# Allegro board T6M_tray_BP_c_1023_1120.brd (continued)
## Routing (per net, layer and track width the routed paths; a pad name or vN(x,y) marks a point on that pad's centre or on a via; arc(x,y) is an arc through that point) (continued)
SAS_BLAD1_TX7_P: length 23.8
  TOP w0.178: U3.B8 171.89,24.81 171.69,24.61 171.69,24.13 v1(172.12,23.7)
  BOTTOM w0.178: J25.G5 166.89,10.86 166.72,11.02 166.25,11.02 arc(166.04,11.07) 165.87,11.18 arc(165.76,11.35) 165.71,11.56 165.71,20.95 arc(165.78,21.28) 165.97,21.55 169,24.59 arc(169.03,24.64) 169.04,24.69 arc(169.11,25.01) 169.29,25.28 169.53,25.53 arc(169.81,25.72) 170.14,25.78 170.73,25.78 arc(170.93,25.74) 171.09,25.63 171.49,25.23 171.66,24.88 171.66,24.16 v1(172.12,23.7)
SAS_BLAD1_TX8_N: length 26.6
  TOP w0.178: U3.B12 168.68,24.81 168.91,24.58 168.91,24.4 168.69,24.18 166.7,24.18 v1(166.22,24.66)
  IN2 w0.152: J25.F6 164.39,8.5 162.78,8.5 arc(162.58,8.54) 162.42,8.65 161.9,9.17 arc(161.79,9.34) 161.75,9.53 161.75,16.91 arc(161.79,17.1) 161.9,17.27 167.31,22.69 arc(167.42,22.85) 167.46,23.04 167.46,23.67 arc(167.42,23.86) 167.31,24.02 167.26,24.08 arc(167.09,24.19) 166.9,24.23 166.65,24.23 v1(166.22,24.66)
SAS_BLAD1_TX8_P: length 27.9
  TOP w0.178: v1(166.22,23.39) 166.65,23.83 168.84,23.83 169.26,24.25 169.26,24.58 169.49,24.81 U3.B11
  IN2 w0.152: J25.E6 164.39,8.1 162.78,8.1 arc(162.43,8.17) 162.13,8.36 161.61,8.89 arc(161.41,9.18) 161.34,9.53 161.34,16.91 arc(161.41,17.26) 161.61,17.56 162,17.95 162,18.19 162.33,18.51 162.57,18.51 162.89,18.84 162.89,19.07 163.21,19.4 163.45,19.4 163.77,19.72 163.77,19.96 164.1,20.28 164.33,20.28 164.66,20.61 164.66,20.84 164.98,21.17 165.22,21.17 165.54,21.49 165.54,21.73 165.87,22.05 166.1,22.05 167.03,22.97 arc(167.05,23.01) 167.06,23.04 167.06,23.67 arc(167.05,23.7) 167.03,23.74 166.97,23.8 arc(166.94,23.82) 166.9,23.83 166.65,23.83 v1(166.22,23.39)
SAS_BLAD2_RX1_N: length 36
  TOP w0.178: v1(415.26,30.56) 415.7,30.12 415.7,29.7 415.49,29.49 U2.A3
  BOTTOM w0.178: J8.E1 396.41,7.18 398.56,7.18 arc(398.62,7.19) 398.67,7.22 413.59,22.15 arc(413.63,22.2) 413.64,22.26 413.64,24.4 arc(413.7,24.73) 413.89,25.01 415.67,26.79 arc(415.71,26.84) 415.72,26.9 415.72,30.1 v1(415.26,30.56)
SAS_BLAD2_RX1_P: length 37.4
  TOP w0.178: v1(416.53,30.56) 416.05,30.09 416.05,29.74 416.3,29.49 U2.A2
  BOTTOM w0.178: J8.D1 396.41,6.82 398.56,6.82 arc(398.75,6.86) 398.92,6.97 404.13,12.19 404.37,12.19 404.75,12.57 404.75,12.81 405.37,13.42 405.61,13.42 405.99,13.8 405.99,14.04 406.37,14.43 406.62,14.43 407,14.81 407,15.05 407.38,15.44 407.63,15.44 408,15.82 408,16.06 408.39,16.45 408.63,16.45 409.01,16.83 409.01,17.07 409.4,17.46 409.64,17.46 410.02,17.83 410.02,18.08 413.84,21.9 arc(413.95,22.06) 413.99,22.26 413.99,24.4 arc(414.03,24.6) 414.14,24.76 415.92,26.54 arc(416.03,26.71) 416.07,26.9 416.07,30.1 v1(416.53,30.56)
SAS_BLAD2_RX2_N: length 36
  TOP w0.178: v1(412.87,31.68) 413.33,31.22 413.33,29.74 413.09,29.5 U2.A6
  IN2 w0.152: v1(412.87,31.68) 413.31,32.11 413.31,32.35 arc(413.3,32.39) 413.28,32.42 413.19,32.51 arc(413.16,32.53) 413.12,32.54 412.64,32.54 arc(412.54,32.53) 412.44,32.5 410.64,31.75 arc(410.59,31.73) 410.55,31.7 410.01,31.34 arc(409.97,31.31) 409.93,31.27 409.5,30.85 arc(409.47,30.81) 409.44,30.77 408.84,29.88 arc(408.82,29.83) 408.8,29.79 408.72,29.59 arc(408.71,29.57) 408.71,29.54 408.71,29.44 arc(408.7,29.34) 408.67,29.25 407.39,26.17 arc(407.35,26.09) 407.28,26.01 406.91,25.64 406.91,25.41 406.59,25.09 406.36,25.09 406.04,24.76 406.04,24.53 405.71,24.21 405.48,24.21 405.16,23.89 405.16,23.66 404.84,23.34 404.61,23.34 404.29,23.01 404.29,22.78 403.96,22.46 403.73,22.46 403.41,22.14 403.41,21.91 403.09,21.59 402.86,21.59 402.54,21.26 402.54,21.03 402.21,20.71 401.99,20.71 401.72,20.44 399.17,18.34 397.07,16.5 394.53,15.34 393.08,13.89 393.05,13.8 393.05,13.07 arc(393.07,12.93) 393.15,12.81 arc(393.27,12.73) 393.41,12.7 393.7,12.7 393.89,12.9 J8.I2
SAS_BLAD2_RX2_P: length 37.1
  TOP w0.178: v1(414.14,31.68) 413.68,31.22 413.68,29.71 413.9,29.5 U2.A5
  IN2 w0.152: v1(414.14,31.68) 413.71,32.11 413.71,32.35 arc(413.67,32.54) 413.56,32.71 413.48,32.79 arc(413.31,32.91) 413.12,32.94 412.64,32.94 arc(412.46,32.93) 412.29,32.87 410.48,32.12 arc(410.4,32.08) 410.32,32.04 409.78,31.67 arc(409.71,31.62) 409.64,31.56 409.22,31.13 arc(409.16,31.07) 409.1,30.99 408.51,30.1 arc(408.46,30.02) 408.42,29.94 408.34,29.75 arc(408.31,29.64) 408.3,29.54 408.3,29.44 arc(408.3,29.42) 408.29,29.4 407.02,26.33 arc(407.01,26.31) 407,26.3 401.45,20.75 arc(401.44,20.74) 401.44,20.74 398.91,18.65 arc(398.91,18.65) 398.9,18.65 398.9,18.64 396.84,16.84 394.29,15.68 392.74,14.12 392.64,13.89 392.64,13.07 arc(392.7,12.77) 392.87,12.52 arc(393.12,12.36) 393.41,12.3 393.69,12.3 393.89,12.1 J8.H2
SAS_BLAD2_RX3_N: length 37.5
  TOP w0.178: U2.A9 410.69,29.5 410.92,29.73 410.92,30.14 v1(410.46,30.59)
  BOTTOM w0.178: J8.C2 393.89,4.46 394.08,4.28 394.46,4.28 arc(394.52,4.29) 394.57,4.32 394.67,4.42 arc(394.7,4.47) 394.72,4.53 394.72,13.38 arc(394.75,13.58) 394.86,13.74 395.3,14.18 arc(395.46,14.29) 395.66,14.33 396.74,14.55 400.11,17.27 arc(400.11,17.27) 400.11,17.27 400.12,17.28 402.58,18.8 406.41,24.82 406.41,24.82 408.58,26.76 arc(408.58,26.76) 408.58,26.76 410.87,29.05 arc(410.91,29.11) 410.92,29.17 410.92,30.13 v1(410.46,30.59)
SAS_BLAD2_RX3_P: length 38.9
  TOP w0.178: U2.A8 411.49,29.5 411.27,29.73 411.27,30.14 v1(411.73,30.59)
  BOTTOM w0.178: J8.B2 393.89,3.68 394.14,3.92 394.46,3.92 arc(394.66,3.96) 394.82,4.07 394.92,4.17 arc(395.03,4.33) 395.07,4.53 395.07,13.38 arc(395.08,13.44) 395.11,13.5 395.55,13.93 arc(395.6,13.96) 395.66,13.98 395.69,13.98 396.9,14.23 400.32,16.99 402.84,18.54 403.22,19.14 403.22,19.14 403.46,19.2 403.74,19.65 403.69,19.89 403.69,19.88 403.98,20.34 403.98,20.35 404.22,20.4 404.51,20.85 404.45,21.09 404.46,21.09 404.75,21.55 404.75,21.55 404.98,21.61 405.27,22.06 405.22,22.29 405.22,22.3 405.51,22.75 405.51,22.76 405.75,22.81 406.03,23.26 405.98,23.5 405.99,23.5 406.68,24.59 408.81,26.5 arc(408.82,26.51) 408.83,26.52 409.1,26.79 409.35,26.79 409.73,27.17 409.73,27.41 410.11,27.8 410.36,27.8 410.73,28.17 410.73,28.42 411.12,28.81 arc(411.23,28.97) 411.27,29.17 411.27,30.14 v1(411.73,30.59)
SAS_BLAD2_RX4_N: length 36.1
  TOP w0.178: U2.A12 408.3,29.5 408.54,29.75 408.54,30.01 408.3,30.25 406.29,30.25 406.04,30 406.04,29.77 v1(406.5,29.31)
  IN2 w0.152: v1(406.5,29.31) 406.07,28.88 406.07,28.51 arc(406.03,28.31) 405.92,28.15 405.76,27.99 arc(405.59,27.88) 405.4,27.84 405,27.84 arc(404.81,27.8) 404.65,27.69 403.65,26.69 arc(403.54,26.53) 403.5,26.33 403.5,25.64 arc(403.43,25.29) 403.23,24.99 402.16,23.92 402.16,23.7 401.84,23.38 401.62,23.38 401.3,23.06 401.3,22.84 400.97,22.51 400.76,22.51 396.73,18.48 arc(396.69,18.45) 396.65,18.42 395.57,17.7 arc(395.53,17.67) 395.48,17.65 394.9,17.41 arc(394.8,17.38) 394.71,17.37 394.21,17.37 arc(394.02,17.33) 393.85,17.22 391.63,15.01 391.22,14.01 391.1,13.26 391.1,7.4 arc(391.11,7.35) 391.14,7.3 391.17,7.27 arc(391.24,7.22) 391.33,7.2 391.74,7.2 391.89,7.36 J8.E3
SAS_BLAD2_RX4_P: length 37.7
  TOP w0.178: v1(405.23,29.31) 405.69,29.77 405.69,30.14 406.15,30.6 408.44,30.6 408.9,30.15 408.9,29.7 409.09,29.5 U2.A11
  IN2 w0.152: J8.D3 391.89,6.66 391.76,6.8 391.33,6.8 arc(391.09,6.85) 390.88,6.98 390.86,7.01 arc(390.73,7.19) 390.69,7.4 390.69,13.29 390.83,14.13 391.29,15.24 393.56,17.51 arc(393.86,17.71) 394.21,17.78 394.71,17.78 arc(394.73,17.78) 394.74,17.79 395.33,18.03 arc(395.33,18.03) 395.34,18.04 396.42,18.76 arc(396.43,18.76) 396.44,18.77 402.94,25.28 arc(403.05,25.44) 403.09,25.64 403.09,26.33 arc(403.16,26.68) 403.36,26.98 404.36,27.98 arc(404.65,28.18) 405,28.24 405.4,28.24 arc(405.44,28.25) 405.47,28.27 405.63,28.44 arc(405.65,28.47) 405.66,28.51 405.66,28.88 v1(405.23,29.31)
SAS_BLAD2_RX5_N: length 28.9
  TOP w0.178: v1(396.25,31) 396.71,30.54 396.71,29.73 396.48,29.5 U4.A3
  IN2 w0.152: v1(396.25,31) 396.68,31.43 396.68,31.75 arc(396.67,31.79) 396.65,31.82 396.48,32 arc(396.44,32.02) 396.41,32.03 396.09,32.03 arc(396.05,32.02) 396.02,32 395.78,31.77 395.44,31.42 394.85,30.83 394.84,30.83 arc(394.82,30.79) 394.81,30.75 394.81,29.85 394.99,29.67 394.99,29.26 394.81,29.09 394.81,28.63 394.99,28.45 394.99,28.05 394.81,27.87 394.81,27.28 394.96,27.13 394.96,26.67 394.81,26.52 394.81,26.14 arc(394.85,25.95) 394.96,25.78 395.04,25.7 arc(395.15,25.54) 395.19,25.34 395.19,23.43 arc(395.15,23.23) 395.04,23.07 394.85,22.87 394.85,22.64 394.52,22.32 394.3,22.32 393.97,22 393.97,21.77 393.65,21.44 393.42,21.44 393.1,21.12 393.1,20.89 392.77,20.57 392.55,20.57 391.86,19.88 arc(391.75,19.72) 391.71,19.53 391.71,17.71 arc(391.67,17.52) 391.56,17.35 389.2,14.98 arc(389.09,14.82) 389.05,14.62 389.05,13.09 arc(389.08,12.94) 389.16,12.82 389.16,12.82 arc(389.28,12.73) 389.43,12.7 389.74,12.7 389.89,12.86 J8.I4
SAS_BLAD2_RX5_P: length 30
  TOP w0.178: U4.A2 397.28,29.5 397.06,29.73 397.06,30.54 v1(397.52,31)
  IN2 w0.152: J8.H4 389.89,12.11 389.7,12.3 389.43,12.3 arc(389.13,12.36) 388.87,12.53 arc(388.7,12.79) 388.64,13.09 388.64,14.62 arc(388.71,14.97) 388.91,15.27 391.28,17.64 arc(391.3,17.67) 391.31,17.71 391.31,19.53 arc(391.38,19.88) 391.58,20.17 394.76,23.35 arc(394.78,23.39) 394.79,23.43 394.79,25.34 arc(394.78,25.38) 394.76,25.41 394.67,25.5 arc(394.48,25.79) 394.41,26.14 394.41,30.75 arc(394.45,30.95) 394.56,31.12 395.15,31.71 395.73,32.29 arc(395.89,32.4) 396.09,32.44 396.41,32.44 arc(396.6,32.4) 396.76,32.29 396.94,32.11 arc(397.05,31.95) 397.09,31.75 397.09,31.43 v1(397.52,31)
SAS_BLAD2_RX6_N: length 34.2
  TOP w0.178: U4.A6 394.08,29.5 394.31,29.73 394.31,32.48 v1(393.88,32.92)
  BOTTOM w0.178: v1(393.88,32.92) 394.34,32.46 394.34,27.43 arc(394.4,27.1) 394.59,26.83 394.67,26.74 arc(394.7,26.69) 394.72,26.63 394.72,22.5 394.71,22.37 394.7,22.32 394.7,22.32 394.44,21.68 arc(394.42,21.65) 394.4,21.63 389.76,16.98 arc(389.73,16.95) 389.72,16.92 389.01,15.2 arc(389,15.19) 389,15.17 388.83,14.46 388.73,14.05 388.72,13.97 388.72,7.37 arc(388.71,7.3) 388.66,7.23 388.66,7.23 arc(388.6,7.19) 388.53,7.18 388.07,7.18 387.89,7.36 J8.E5
SAS_BLAD2_RX6_P: length 35.6
  TOP w0.178: U4.A5 394.88,29.5 394.66,29.73 394.66,32.43 v1(395.15,32.92)
  BOTTOM w0.178: v1(395.15,32.92) 394.69,32.46 394.69,31.47 394.86,31.3 394.86,30.76 394.69,30.59 394.69,28.67 394.86,28.5 394.86,27.97 394.69,27.79 394.69,27.43 arc(394.72,27.24) 394.83,27.07 394.92,26.99 arc(395.03,26.83) 395.07,26.63 395.07,26.22 395.24,26.05 395.24,25.52 395.07,25.34 395.07,24.8 395.24,24.62 395.24,24.09 395.07,23.92 395.07,23.37 395.24,23.2 395.24,22.66 395.07,22.49 395.06,22.33 395.03,22.18 394.76,21.54 arc(394.72,21.46) 394.65,21.38 394.54,21.26 394.33,21.06 394.33,20.82 393.96,20.44 393.71,20.44 390.03,16.76 389.34,15.08 389.07,13.97 389.07,7.37 arc(389.03,7.16) 388.91,6.98 388.91,6.98 arc(388.74,6.86) 388.53,6.82 388.08,6.82 387.89,6.63 J8.D5
SAS_BLAD2_RX7_N: length 33.9
  TOP w0.178: v1(391.45,31.99) 391.91,31.53 391.91,29.73 391.68,29.5 U4.A9
  IN2 w0.152: v1(391.45,31.99) 391.88,32.42 391.88,32.77 arc(391.87,32.81) 391.85,32.84 391.73,32.96 arc(391.69,32.99) 391.66,32.99 390.25,32.99 arc(390.05,32.96) 389.89,32.85 387.65,30.6 arc(387.54,30.44) 387.5,30.24 387.5,28.76 arc(387.54,28.57) 387.65,28.4 388.69,27.36 388.8,27.36 388.92,27.36 389.24,27.04 389.24,26.8 390.29,25.75 arc(390.4,25.59) 390.44,25.39 390.44,22.74 arc(390.37,22.39) 390.18,22.09 389.95,21.87 389.95,21.74 389.95,21.61 389.63,21.29 389.37,21.29 389.04,20.96 389.04,20.83 389.04,20.7 388.72,20.38 388.46,20.38 386.45,18.37 386.45,18.24 386.45,18.11 386.13,17.79 385.87,17.79 385.54,17.46 385.54,17.33 385.54,17.2 385.22,16.88 384.96,16.88 384.75,16.67 arc(384.64,16.5) 384.6,16.31 384.6,13.04 arc(384.63,12.91) 384.7,12.8 arc(384.81,12.73) 384.94,12.7 385.7,12.7 385.89,12.9 J8.I6
SAS_BLAD2_RX7_P: length 35.1
  TOP w0.178: v1(392.72,31.99) 392.26,31.53 392.26,29.73 392.48,29.5 U4.A8
  IN2 w0.152: v1(392.72,31.99) 392.29,32.42 392.29,32.77 arc(392.25,32.96) 392.14,33.13 392.01,33.25 arc(391.85,33.36) 391.66,33.4 390.25,33.4 arc(389.9,33.33) 389.6,33.13 387.36,30.89 arc(387.16,30.59) 387.09,30.24 387.09,28.76 arc(387.16,28.41) 387.36,28.11 390.01,25.46 arc(390.03,25.43) 390.04,25.39 390.04,22.74 arc(390,22.55) 389.89,22.38 384.46,16.96 arc(384.26,16.66) 384.2,16.31 384.2,13.04 arc(384.25,12.76) 384.41,12.52 arc(384.66,12.35) 384.94,12.3 385.72,12.3 385.89,12.12 J8.H6
SAS_BLAD2_RX8_N: length 35.5
  TOP w0.178: v1(389.05,30.73) 389.51,30.27 389.51,29.73 389.28,29.5 U4.A12
  BOTTOM w0.178: v1(389.05,30.73) 389.51,31.19 389.51,31.51 arc(389.5,31.57) 389.46,31.62 389.46,31.63 arc(389.4,31.67) 389.34,31.68 388.75,31.68 arc(388.56,31.64) 388.39,31.53 387.39,30.52 arc(387.28,30.36) 387.24,30.16 387.24,27.21 arc(387.2,27.01) 387.09,26.85 384.47,24.22 arc(384.36,24.06) 384.32,23.86 384.32,23.14 384.49,22.97 384.49,22.44 384.32,22.26 384.32,21.73 384.49,21.56 384.49,21.02 384.32,20.85 384.32,4.94 arc(384.36,4.75) 384.47,4.58 384.62,4.42 arc(384.79,4.31) 384.98,4.28 385.37,4.28 J8.C6
SAS_BLAD2_RX8_P: length 36.8
  TOP w0.178: U4.A11 390.08,29.5 389.86,29.73 389.86,30.27 v1(390.32,30.73)
  BOTTOM w0.178: v1(390.32,30.73) 389.86,31.19 389.86,31.51 arc(389.82,31.71) 389.71,31.87 389.7,31.88 arc(389.54,31.99) 389.34,32.03 388.75,32.03 arc(388.43,31.96) 388.15,31.78 387.14,30.77 arc(386.95,30.49) 386.89,30.16 386.89,27.21 arc(386.88,27.15) 386.84,27.09 384.22,24.47 arc(384.03,24.19) 383.97,23.86 383.97,4.94 arc(384.03,4.61) 384.22,4.33 384.37,4.18 arc(384.65,3.99) 384.98,3.92 385.37,3.92 J8.B6
SAS_BLAD2_TX1_N: length 39.6
  TOP w0.178: v1(418.66,23.4) 418.21,23.85 416.53,23.85 416.12,24.26 416.12,24.58 415.9,24.81 U2.B3
  IN2 w0.152: v1(418.66,23.4) 419.09,23.83 419.41,23.83 arc(419.53,23.81) 419.64,23.74 arc(419.71,23.64) 419.73,23.52 419.73,22.94 arc(419.73,22.92) 419.72,22.9 419.15,21.53 arc(419.15,21.52) 419.14,21.51 413.78,13.48 413.77,13.47 406.46,6.16 arc(406.44,6.14) 406.41,6.12 arc(406.4,6.11) 406.39,6.11 arc(406.37,6.1) 406.36,6.09 399.01,3.04 arc(398.92,3.01) 398.82,3 396.39,3 J8.B1
SAS_BLAD2_TX1_P: length 41.1
  TOP w0.178: U2.B2 416.69,24.81 416.47,24.58 416.47,24.41 416.68,24.2 418.19,24.2 v1(418.66,24.67)
  IN2 w0.152: v1(418.66,24.67) 419.09,24.24 419.41,24.24 arc(419.69,24.18) 419.92,24.03 arc(420.08,23.79) 420.14,23.52 420.14,22.94 arc(420.13,22.84) 420.1,22.75 419.53,21.37 arc(419.51,21.33) 419.48,21.28 419.48,21.28 414.11,13.25 414.09,13.21 413.05,12.18 413.05,11.94 412.73,11.62 412.49,11.62 412.17,11.3 412.17,11.06 411.85,10.73 411.61,10.73 411.28,10.41 411.28,10.17 410.96,9.85 410.72,9.85 410.4,9.53 410.4,9.29 410.08,8.96 409.84,8.96 409.52,8.64 409.52,8.4 409.19,8.08 408.95,8.08 408.63,7.76 408.63,7.52 408.31,7.2 408.07,7.2 406.74,5.87 arc(406.69,5.83) 406.64,5.78 arc(406.61,5.77) 406.58,5.75 arc(406.55,5.73) 406.52,5.72 399.17,2.66 arc(398.99,2.61) 398.82,2.59 396.38,2.59 J8.A1
SAS_BLAD2_TX2_N: length 29.4
  TOP w0.178: U2.B6 413.49,24.99 413.72,24.76 413.72,18.98 v1(413.26,18.52)
  IN2 w0.152: v1(413.26,18.52) 413.69,18.08 413.69,17.62 arc(413.65,17.42) 413.54,17.26 407.84,11.55 arc(407.67,11.44) 407.48,11.4 396.39,11.4 J8.H1
SAS_BLAD2_TX2_P: length 30.5
  TOP w0.178: v1(414.53,18.52) 414.07,18.98 414.07,24.76 414.3,24.99 U2.B5
  IN2 w0.152: J8.G1 396.39,11 400.03,11 400.2,10.82 400.66,10.82 400.84,11 401.3,11 401.47,10.82 401.93,10.82 402.1,11 402.56,11 402.74,10.82 403.2,10.82 403.37,11 407.48,11 arc(407.83,11.07) 408.13,11.26 413.83,16.97 arc(414.03,17.27) 414.1,17.62 414.1,18.09 v1(414.53,18.52)
SAS_BLAD2_TX3_N: length 30.3
  TOP w0.178: v1(410.86,23.58) 411.32,24.04 411.32,24.58 411.09,24.81 U2.B9
  IN2 w0.152: J8.F2 393.89,8.73 394.12,8.5 394.5,8.5 arc(394.57,8.52) 394.63,8.56 arc(394.68,8.62) 394.69,8.7 394.69,13.28 arc(394.76,13.63) 394.96,13.93 395.14,14.11 arc(395.43,14.31) 395.78,14.38 403.14,14.38 arc(403.33,14.42) 403.5,14.53 411.14,22.17 arc(411.25,22.34) 411.29,22.53 411.29,23.15 v1(410.86,23.58)
SAS_BLAD2_TX3_P: length 31.6
  TOP w0.178: U2.B8 411.9,24.81 411.67,24.58 411.67,24.04 v1(412.13,23.58)
  IN2 w0.152: v1(412.13,23.58) 411.7,23.15 411.7,22.53 arc(411.63,22.18) 411.43,21.89 403.78,14.24 arc(403.49,14.04) 403.14,13.97 402.74,13.97 402.59,13.82 402.13,13.82 401.98,13.97 401.52,13.97 401.37,13.82 400.91,13.82 400.76,13.97 400.3,13.97 400.15,13.82 399.69,13.82 399.54,13.97 399.08,13.97 398.93,13.82 398.47,13.82 398.32,13.97 397.86,13.97 397.71,13.82 397.25,13.82 397.1,13.97 395.78,13.97 arc(395.59,13.93) 395.43,13.82 395.25,13.64 arc(395.14,13.48) 395.1,13.28 395.1,8.7 arc(395.05,8.47) 394.92,8.27 arc(394.73,8.14) 394.5,8.1 394.09,8.1 393.89,7.89 J8.E2
SAS_BLAD2_TX4_N: length 34.3
  TOP w0.178: v1(406.27,26.82) 405.81,26.37 405.81,25.08 407.15,23.74 408.56,23.74 408.92,24.1 408.92,24.58 408.69,24.81 U2.B12
  BOTTOM w0.178: J8.H3 391.89,11.56 392.08,11.38 392.53,11.38 arc(392.6,11.39) 392.66,11.43 arc(392.7,11.49) 392.71,11.56 392.71,13.98 392.95,14.56 394.39,16 arc(394.67,16.19) 395,16.25 395.26,16.25 arc(395.28,16.25) 395.29,16.26 396.11,16.6 arc(396.14,16.61) 396.16,16.63 398.71,19.18 arc(398.99,19.37) 399.32,19.43 399.6,19.43 arc(399.62,19.43) 399.64,19.44 400.42,19.76 arc(400.45,19.78) 400.47,19.8 401.62,20.95 arc(401.64,20.97) 401.66,21 402.6,23.28 arc(402.61,23.31) 402.62,23.34 402.62,26.54 arc(402.68,26.86) 402.87,27.14 403.77,28.04 arc(404.05,28.23) 404.37,28.3 405.09,28.3 arc(405.29,28.26) 405.45,28.15 405.66,27.94 arc(405.77,27.77) 405.81,27.58 405.81,27.28 v1(406.27,26.82)
SAS_BLAD2_TX4_P: length 35.4
  TOP w0.178: v1(405,26.82) 405.46,26.36 405.46,24.94 407,23.39 408.71,23.39 409.27,23.96 409.27,24.58 409.49,24.81 U2.B11
  BOTTOM w0.178: v1(405,26.82) 405.46,27.28 405.46,27.58 arc(405.45,27.64) 405.41,27.69 405.2,27.9 arc(405.15,27.93) 405.09,27.95 404.37,27.95 arc(404.18,27.91) 404.02,27.8 403.11,26.9 arc(403,26.73) 402.97,26.54 402.97,26.22 403.14,26.04 403.14,25.51 402.97,25.34 402.97,24.79 403.14,24.62 403.14,24.09 402.97,23.91 402.97,23.34 arc(402.96,23.24) 402.93,23.15 401.98,20.86 arc(401.93,20.78) 401.87,20.7 400.72,19.55 arc(400.64,19.48) 400.56,19.44 399.78,19.11 arc(399.69,19.09) 399.6,19.08 399.32,19.08 arc(399.13,19.04) 398.96,18.93 398.64,18.61 398.64,18.4 398.27,18.02 398.05,18.02 396.41,16.38 arc(396.34,16.32) 396.25,16.27 395.43,15.93 arc(395.35,15.91) 395.26,15.9 395,15.9 arc(394.8,15.86) 394.64,15.75 393.25,14.36 393.06,13.91 393.06,11.55 arc(393.02,11.35) 392.91,11.18 arc(392.73,11.07) 392.53,11.02 392,11.02 391.89,10.92 J8.G3
SAS_BLAD2_TX5_N: length 26.8
  TOP w0.178: v1(399.22,23.39) 398.79,23.83 397.54,23.83 397.11,24.26 397.11,24.58 396.88,24.81 U4.B3
  BOTTOM w0.178: v1(399.22,23.39) 399.68,23.85 399.99,23.85 arc(400.05,23.84) 400.1,23.81 400.21,23.7 arc(400.24,23.65) 400.25,23.59 400.25,22.8 arc(400.21,22.6) 400.1,22.44 399.2,21.54 arc(399.04,21.43) 398.84,21.39 397.52,21.39 arc(397.33,21.35) 397.16,21.24 394.11,18.18 arc(394.08,18.16) 394.05,18.16 arc(393.75,18.1) 393.5,17.93 391.35,15.78 arc(391.33,15.75) 391.31,15.72 390.92,14.77 arc(390.91,14.76) 390.91,14.75 390.9,14.7 390.72,13.98 390.71,13.89 390.71,8.66 arc(390.7,8.59) 390.66,8.53 arc(390.59,8.49) 390.52,8.48 390.08,8.48 389.89,8.66 J8.F4
SAS_BLAD2_TX5_P: length 28
  TOP w0.178: U4.B2 397.68,24.81 397.46,24.58 397.46,24.41 397.69,24.18 398.74,24.18 v1(399.22,24.66)
  BOTTOM w0.178: v1(399.22,24.66) 399.68,24.2 399.99,24.2 arc(400.18,24.16) 400.35,24.05 400.45,23.95 arc(400.56,23.78) 400.6,23.59 400.6,22.8 arc(400.54,22.47) 400.35,22.19 400.19,22.02 400.19,21.78 399.81,21.4 399.57,21.4 399.45,21.29 arc(399.17,21.1) 398.84,21.04 398.64,21.04 398.47,20.86 397.93,20.86 397.76,21.04 397.52,21.04 arc(397.46,21.02) 397.41,20.99 397.16,20.73 397.16,20.49 396.78,20.11 396.53,20.11 396.53,20.11 396.15,19.72 396.15,19.48 395.77,19.1 395.53,19.1 395.14,18.72 395.14,18.47 394.76,18.09 394.52,18.09 394.35,17.93 arc(394.21,17.84) 394.05,17.81 arc(393.89,17.77) 393.75,17.68 391.62,15.55 391.25,14.65 391.06,13.89 391.06,8.66 arc(391.02,8.46) 390.9,8.28 arc(390.73,8.17) 390.52,8.12 390.1,8.12 389.89,7.91 J8.E4
SAS_BLAD2_TX6_N: length 32.1
  TOP w0.178: v1(389.73,18.52) 389.22,18.01 389.22,17.83 389.45,17.6 392.33,17.6 arc(392.39,17.61) 392.44,17.65 392.44,17.65 arc(392.72,17.84) 393.05,17.9 393.77,17.9 arc(393.83,17.91) 393.88,17.95 394.66,18.73 arc(394.7,18.78) 394.71,18.84 394.71,24.58 394.48,24.81 U4.B6
  IN2 w0.152: J8.B5 387.89,3.11 387.78,3 387.34,3 arc(387.25,3.02) 387.16,3.08 arc(387.11,3.16) 387.09,3.26 387.09,14.33 387.27,14.51 387.27,14.97 387.09,15.15 387.09,15.48 arc(387.1,15.52) 387.12,15.56 387.55,15.99 387.77,15.99 388.09,16.31 388.09,16.53 389.12,17.56 arc(389.26,17.76) 389.3,18 arc(389.3,18.04) 389.3,18.08 389.3,18.08 v1(389.73,18.52)
SAS_BLAD2_TX6_P: length 33.5
  TOP w0.178: v1(388.46,18.52) 388.87,18.11 388.87,17.68 389.3,17.25 392.33,17.25 arc(392.52,17.29) 392.69,17.4 392.69,17.4 arc(392.85,17.51) 393.05,17.55 393.77,17.55 arc(393.96,17.59) 394.13,17.7 394.91,18.48 arc(395.02,18.65) 395.06,18.84 395.06,24.58 395.28,24.81 U4.B5
  IN2 w0.152: v1(388.46,18.52) 388.83,18.15 arc(388.88,18.08) 388.9,18 arc(388.88,17.92) 388.83,17.85 386.83,15.84 arc(386.72,15.68) 386.68,15.48 386.68,3.26 arc(386.73,3) 386.88,2.79 arc(387.09,2.65) 387.34,2.6 387.77,2.6 387.89,2.48 J8.A5
SAS_BLAD2_TX7_N: length 22.7
  TOP w0.178: U4.B9 392.08,24.86 392.34,24.61 392.34,24.18 v1(391.85,23.7)
  BOTTOM w0.178: v1(391.85,23.7) 392.31,24.16 392.31,24.8 392.2,25.03 391.84,25.38 arc(391.79,25.42) 391.73,25.43 391.14,25.43 arc(390.95,25.39) 390.78,25.28 390.54,25.04 arc(390.43,24.88) 390.39,24.69 arc(390.36,24.5) 390.25,24.34 387.21,21.31 arc(387.1,21.14) 387.07,20.95 387.07,20.7 387.24,20.53 387.24,19.99 387.07,19.82 387.07,19.29 387.24,19.11 387.24,18.58 387.07,18.41 387.07,17.87 387.24,17.7 387.24,17.17 387.07,17 387.07,11.56 arc(387.08,11.49) 387.12,11.43 arc(387.18,11.39) 387.25,11.38 387.77,11.38 387.89,11.49 J8.H5
SAS_BLAD2_TX7_P: length 23.8
  TOP w0.178: v1(393.12,23.7) 392.69,24.13 392.69,24.61 392.88,24.81 U4.B8
  BOTTOM w0.178: J8.G5 387.89,10.86 387.72,11.02 387.25,11.02 arc(387.04,11.07) 386.87,11.18 arc(386.76,11.35) 386.71,11.56 386.71,20.95 arc(386.78,21.28) 386.97,21.55 390,24.59 arc(390.03,24.64) 390.04,24.69 arc(390.11,25.01) 390.29,25.28 390.53,25.53 arc(390.81,25.72) 391.14,25.78 391.73,25.78 arc(391.93,25.74) 392.09,25.63 392.49,25.23 392.66,24.88 392.66,24.16 v1(393.12,23.7)
SAS_BLAD2_TX8_N: length 26.6
  TOP w0.178: v1(387.22,24.66) 387.7,24.18 389.69,24.18 389.91,24.4 389.91,24.58 389.68,24.81 U4.B12
  IN2 w0.152: v1(387.22,24.66) 387.65,24.23 387.9,24.23 arc(388.09,24.19) 388.26,24.08 388.31,24.02 arc(388.42,23.86) 388.46,23.67 388.46,23.04 arc(388.42,22.85) 388.31,22.69 382.9,17.27 arc(382.79,17.1) 382.75,16.91 382.75,9.53 arc(382.79,9.34) 382.9,9.17 383.42,8.65 arc(383.58,8.54) 383.78,8.5 385.39,8.5 J8.F6
SAS_BLAD2_TX8_P: length 27.9
  TOP w0.178: v1(387.22,23.39) 387.65,23.83 389.84,23.83 390.26,24.25 390.26,24.58 390.48,24.81 U4.B11
  IN2 w0.152: J8.E6 385.39,8.1 383.78,8.1 arc(383.43,8.17) 383.13,8.36 382.61,8.89 arc(382.41,9.18) 382.34,9.53 382.34,16.91 arc(382.41,17.26) 382.61,17.56 383,17.95 383,18.19 383.33,18.51 383.57,18.51 383.89,18.84 383.89,19.07 384.21,19.4 384.45,19.4 384.77,19.72 384.77,19.96 385.1,20.28 385.33,20.28 385.66,20.61 385.66,20.84 385.98,21.17 386.22,21.17 386.54,21.49 386.54,21.73 386.87,22.05 387.1,22.05 388.03,22.97 arc(388.05,23.01) 388.06,23.04 388.06,23.67 arc(388.05,23.7) 388.03,23.74 387.97,23.8 arc(387.94,23.82) 387.9,23.83 387.65,23.83 v1(387.22,23.39)
SFP1_PRESENT_N: length 11.5
  TOP w0.29: J24.I2 128.23,14.9 v3(128.23,19.99) R58.2 128.82,21.35 129.03,21.14 R66.2 R67.2
SFP2_PRESENT_N: length 12.3
  TOP w0.29: R59.2 119.83,22.62 R68.2 R69.2 v3(119.83,19.91) 119.83,17.75 119.56,17.48 119.56,12.87 J24.H5
SFP3_PRESENT_N: length 11.1
  TOP w0.29: J7.I2 349.59,15.26 v3(349.59,19.99) R71.2 350.19,21.16 350.26,21.09 R75.2 R70.2
SFP4_PRESENT_N: length 11.9
  TOP w0.29: R72.2 R73.2 ; R73.2 v3(340.66,19.91) 340.66,12.77 J7.H5 ; R73.2 341.11,21.15 341.35,21.39 R74.2
SKU_PIN_BLAD1_1: length 14
  TOP w0.29: J24.F3 125.45,10.02 125.45,13.49 126.05,14.08 v3(126.05,19.96) R39.1 R38.2
SKU_PIN_BLAD1_2: length 9.8
  TOP w0.29: J24.I4 122.53,18.65 v3(123.84,19.96) R56.2 R57.1
SKU_PIN_BLAD2_1: length 14
  TOP w0.29: J7.F3 346.52,10.09 346.52,15.2 346.94,15.62 346.94,18.69 346.52,19.11 v3(346.52,19.99) R64.2 R65.1
SKU_PIN_BLAD2_2: length 10
  TOP w0.29: R61.1 R60.2 345.43,20.56 v3(344.86,19.99) 343.53,18.66 J7.I4
N39386877: length 11.5
  TOP w0.29: R84.1 v1(28.44,18.69) R85.1
  IN1 w0.183: JP3.2 27.76,25.52 26.64,24.41 26.64,22.76 27.69,21.72 27.69,19.45 v1(28.44,18.69)
N39391900: length 33.4
  TOP w0.29: R87.1 v1(30.98,18.01) R86.1
  BOTTOM w0.29: v1(30.98,18.01) 30.95,18.03 28.24,18.03 27.17,19.11 24.98,19.11 23.6,20.5 19.74,20.5 19.51,20.73 8.15,20.73 6.86,22.02 3.64,22.02 JP4.2
N39395053: length 9.4
  TOP w0.29: R88.1 v1(29.71,17.42) R89.1
  IN1 w0.183: JP7.2 27.76,22.36 29.26,20.85 29.26,20.78 29.71,20.33 v1(29.71,17.42)
N39398095: length 30.4
  TOP w0.29: R91.1 v1(27.17,17.4) R90.1
  BOTTOM w0.29: JP8.2 4.02,18.65 7.59,18.65 11.02,15.21 24.98,15.21 v1(27.17,17.4)

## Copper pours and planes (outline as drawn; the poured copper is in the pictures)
GND on TOP (solid shape): 146.76,2.54 146.76,1.65 146.56,1.45 142.7,1.45 142.44,1.7 142.44,2.72 142.62,2.9 146.41,2.9
GND on TOP (solid shape): 160.05,27.43 160.05,22.05 159.79,21.79 158.29,21.79 157.94,22.15 157.94,27.36 158.34,27.76 159.72,27.76
GND on TOP (solid shape): 327.63,2.13 327.63,1.55 327.38,1.3 322.68,1.3 322.4,1.57 322.4,2.21 322.63,2.44 327.33,2.44
GND on TOP (solid shape): 380.95,28.42 380.95,22.71 380.62,22.38 379.2,22.38 378.64,22.94 378.64,28.47 378.94,28.78 380.59,28.78
GND on TOP (solid shape): 426.21,29.77 426.21,20.04 425.81,19.63 424.99,19.63 424.66,19.96 424.66,29.59 425.09,30.02 425.96,30.02
GND on TOP (solid shape): 31.78,15.9 31.78,14.63 31.5,14.35 25.7,14.35 25.45,14.61 25.45,16 25.6,16.15 31.52,16.15
GND on TOP (solid shape): 106.53,2.59 106.53,1.6 106.25,1.32 102.06,1.32 101.93,1.45 101.93,2.62 102.12,2.81 104.2,2.81 104.22,2.82 106.3,2.82
GND on TOP (solid shape): 366.42,3.04 367.72,3.04 367.92,2.84 367.92,1.93 367.61,1.63 363.98,1.63 363.73,1.88 363.73,2.87 363.87,3.02 365.23,3.02 365.3,3.02 365.38,3.04 365.4,3.05 366.34,3.05
GND on TOP (solid shape): 202.97,43.7 203.37,43.7 203.37,41.46 202.97,41.46 202.97,28.69 203.37,28.69 203.37,26.48 202.97,26.48 202.97,19.91 196.06,19.91 196.06,22.02 200.4,22.02 200.4,26.3 199.82,26.3 199.82,28.89 200.39,28.89 200.39,32.68 199.92,32.68 199.92,34.53 200.38,34.53 200.38,41.31 199.82,41.31 199.82,43.83 200.37,43.83 200.37,46.19 182.62,46.19 182.62,22.02 187.35,22.02 187.35,19.91 177.06,19.91 177.06,22.02 181.35,22.02 181.35,46.19 163.61,46.19 163.61,43.85 164.16,43.85 164.16,41.34 163.61,41.34 163.61,34.5 164.06,34.5 164.06,32.68 163.61,32.68 163.61,28.84 164.16,28.84 164.16,26.33 163.61,26.33 163.61,22.02 168.32,22.02 168.32,19.91 161,19.91 161,26.48 160.6,26.48 160.6,28.71 161,28.71 161,41.46 160.6,41.46 160.6,43.7 161,43.7 161,50.39 202.97,50.39
GND on TOP (solid shape): 423.97,43.7 424.37,43.7 424.37,41.46 423.97,41.46 423.97,28.69 424.37,28.69 424.37,26.48 423.97,26.48 423.97,19.91 417.06,19.91 417.06,22.02 421.4,22.02 421.4,26.3 420.82,26.3 420.82,28.89 421.39,28.89 421.39,32.68 420.92,32.68 420.92,34.53 421.38,34.53 421.38,41.31 420.82,41.31 420.82,43.83 421.37,43.83 421.37,46.19 403.62,46.19 403.62,22.02 408.35,22.02 408.35,19.91 398.06,19.91 398.06,22.02 402.35,22.02 402.35,46.19 384.61,46.19 384.61,43.85 385.16,43.85 385.16,41.34 384.61,41.34 384.61,34.5 385.06,34.5 385.06,32.68 384.61,32.68 384.61,28.84 385.16,28.84 385.16,26.33 384.61,26.33 384.61,22.02 389.32,22.02 389.32,19.91 382,19.91 382,26.48 381.6,26.48 381.6,28.71 382,28.71 382,41.46 381.6,41.46 381.6,43.7 382,43.7 382,50.39 423.97,50.39
GND on TOP (solid shape): outline of 235 points within 307.24,23.39 371.3,50.77
GND on TOP (solid shape): outline of 258 points within -0.01,0.19 9.01,9.21
GND on TOP (solid shape): outline of 258 points within 419.8,0.19 428.82,9.21
GND on TOP (solid shape): outline of 316 points within 0.5,25 8.5,39
GND on TOP (solid shape): outline of 316 points within 75.81,37.5 83.81,51.5
GND on TOP (solid shape): outline of 316 points within 195.05,0.7 203.05,14.7
GND on TOP (solid shape): outline of 316 points within 205.81,37.5 213.81,51.5
GND on TOP (solid shape): outline of 316 points within 275.81,0.7 283.81,14.7
GND on TOP (solid shape): outline of 316 points within 296.81,37.5 304.81,51.5
GND on TOP (solid shape): outline of 1451 points within 31.41,1.98 150.7,51.61
GND on BOTTOM (solid shape): outline of 263 points within 0,0.2 9,15.2
GND on BOTTOM (solid shape): outline of 263 points within 419.81,0.2 428.81,15.2
GND on BOTTOM (solid shape): outline of 316 points within 0.5,25 8.5,39
GND on BOTTOM (solid shape): outline of 316 points within 75.81,37.5 83.81,51.5
GND on BOTTOM (solid shape): outline of 316 points within 195.05,0.7 203.05,14.7
GND on BOTTOM (solid shape): outline of 316 points within 205.81,37.5 213.81,51.5
GND on BOTTOM (solid shape): outline of 316 points within 275.81,0.7 283.81,14.7
GND on BOTTOM (solid shape): outline of 316 points within 296.81,37.5 304.81,51.5
GND on BOTTOM (solid shape): outline of 15119 points within 0.79,1.52 426.31,51.61
GND on GND (solid shape): outline of 4989 points within 0.51,0.51 428.3,51.81
GND on IN1 (solid shape): outline of 20232 points within 1.47,1.78 423.42,50.52
GND on IN2 (solid shape): outline of 2729 points within 199.39,1.78 316.47,34.4
GND on IN2 (solid shape): outline of 11333 points within 2.18,1.52 425.55,50.47
GND on GND1 (solid shape): outline of 4851 points within 0.51,0.51 428.3,51.81
P3V3_BLAD1 on TOP (solid shape): 155.78,43.89 155.78,28.09 154.74,27.05 154.74,22 154.46,21.72 152.15,21.72 151.61,22.25 151.61,43.69 152.17,44.25 155.42,44.25
P3V3_BLAD1 on TOP (solid shape): 95.66,38.86 95.66,26.21 95.07,25.63 92.74,25.63 92.27,26.1 92.27,27.09 92.25,27.1 92.25,29.49 91.41,30.33 91.41,38.99 91.72,39.29 95.22,39.29
P3V3_BLAD1 on TOP (solid shape): 130.28,28.09 130.28,27.08 130,26.8 130,22.86 129.92,22.68 129.74,22.61 129.69,22.61 129.63,22.59 129.39,22.59 129.39,22.39 129.38,22.37 129.36,22.29 129.35,22.21 129.35,22.02 129.31,21.93 129.22,21.89 128.97,21.89 128.79,21.97 128.71,22.15 128.71,22.49 128.79,22.57 128.79,23.25 128.11,23.25 127.75,22.89 127.75,22.76 127.71,22.67 127.62,22.63 127.14,22.63 126.97,22.6 126.82,22.51 126.76,22.51 126.76,22.45 126.74,22.42 126.68,22.29 126.66,22.15 126.58,21.97 126.4,21.89 125.63,21.89 124.09,23.43 123.42,23.43 123.27,23.29 123.27,22 123.06,21.79 122.2,21.79 122.01,21.98 122.01,23.63 121.67,23.98 119.71,23.98 118.37,22.64 118.33,22.63 118.04,22.39 118.09,22.01 118.11,21.98 118.11,21.92 118.07,21.83 117.98,21.79 117.75,21.79 117.47,22.07 117.47,28.04 117.91,28.47 129.9,28.47
P3V3_BLAD1 on IN1 (solid shape): outline of 1142 points within 92.23,1.78 118.8,33.27
P3V3_BLAD1 on IN1 (solid shape): outline of 2425 points within 129.16,1.5 154.28,29.01
P3V3_BLAD2 on TOP (solid shape): 376.78,44.15 376.78,29.21 375.67,28.09 375.67,22.76 375.34,22.43 372.67,22.43 372.14,22.96 372.14,43.94 372.8,44.6 376.33,44.6
P3V3_BLAD2 on TOP (solid shape): 316.38,39.37 316.38,26.01 316.13,25.76 313.41,25.76 313.25,25.92 313.25,27.34 313.23,27.36 313.23,30.63 312.34,31.52 312.34,39.42 312.83,39.9 315.85,39.9
P3V3_BLAD2 on TOP (solid shape): 351.1,26.82 351.1,22.67 351.07,22.58 350.98,22.54 350.9,22.54 350.88,22.55 350.78,22.56 350.67,22.55 350.66,22.54 350.44,22.54 350.35,22.58 350.32,22.67 350.32,23.11 349.72,23.71 345.17,23.71 345.04,23.57 345.01,23.56 344.72,23.22 344.83,22.79 344.83,22.02 344.58,21.77 343.97,21.77 343.79,21.95 343.79,22.52 343.43,22.88 341.92,22.88 341.27,23.52 341.12,23.52 341.1,23.55 340.46,23.55 340.18,23.45 340,23.21 339.99,23.18 339.29,22.48 339.29,22.24 338.56,21.51 338.47,21.47 338.39,21.51 338.3,21.59 338.3,26.92 338.68,27.3 350.62,27.3
P3V3_BLAD2 on IN1 (solid shape): outline of 1124 points within 313.18,2.21 339.88,33.05
P3V3_BLAD2 on IN1 (solid shape): outline of 2476 points within 347.83,1.52 375.54,27.69
P12V on TOP (solid shape): 94.67,21.01 94.67,2.62 93.68,1.63 90.4,1.63 89.31,2.72 89.31,7.89 89.34,7.98 89.42,8.02 90.81,9.5 89.42,10.98 89.34,11.02 89.31,11.11 89.31,15.54 86.97,17.88 86.97,22.76 87.4,23.19 92.48,23.19
P12V on TOP (solid shape): outline of 3568 points within 1.47,1.57 70.92,51.74
P12V on TOP (solid shape): outline of 3846 points within 203.85,1.78 316.99,50.32
P12V on BOTTOM (solid shape): 21.43,51.86 30.64,51.86 30.84,51.66 30.84,45.45 30.9,45.39 30.9,35.8 30.28,35.18 28.05,35.18 28.01,35.19 27.97,35.21 27.73,35.33 27.46,35.29 27.43,35.27 24.22,35.27 19.22,40.28 13.59,40.28 12.48,41.39 11.86,41.39 11.77,41.42 11.73,41.51 11.73,51.46 12.14,51.86 20.56,51.86 20.65,51.83 20.68,51.74 20.68,45.45 21.23,45.45 21.23,51.74 21.27,51.83 21.36,51.86 21.43,51.86
P12V on VCC (solid shape): outline of 4679 points within 1.02,1.02 427.79,51.3
P12V on VCC1 (solid shape): outline of 4678 points within 1.02,1.02 427.79,51.3

Small or netless copper shapes (teardrops, artwork), in the pictures only: 76 on BOTTOM

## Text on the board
User.Comments: TEL:(03)327-2345 FAX:(03)397-3614 | PROJECT: | P/N: | DATE: | REV: | NO.188,WEN HWA 2ND RD. | KUEI SHAN HSIANG,TAO YUAN | SHIEN,TAIWAN R.O.C. | Layer | Irene | DA0T6MTH8C0 | 2012/10/23 | T6M_Tray_BP | C | 16 | Quanta
Ref Des/Silkscreen Top: Node 3 | Node 1 | Node 2 | Node 4 | A | D | B | C | SFP+ | CONN2 | CONN3 | POWER CONN | CONN1 | LAN1~2 | LAN | AIRMAX | SAS | 4~7 | 0~3 | CONN4 | LAN3~4 | P/N:DA0T6MTH8C0 | Rev:C
DISPLAY_TOP: 2 | 4 | 6 | 7 | 3 | 5 | 1 | A | B | C | D | E | F | G | 100- | RANGE | 10-50 | 50-100 | 0-10 | TOLERANCE | ` | 0.25 | 0.15 | 0.20 | 0.10 | H | I | APPROVED | DESIGNED | DRAWN | J | 53.3 | 35 | 0 | 5.3 | n | REF | 6X | 9 | 4X | 47 | 4.7 | 52.32 | 1.6 | 4.98 | 177.76 | 200.98 | 395.98 | 400.98
DISPLAY_BOTTOM: 0 | 3.6 | n | 3.5 | 6X | 52.32 | 8X | 9 | 1.6 | 399.96
User.5: 8X | 9 | n
User.6: 0 | 3.6 | n | 3.5 | 6X | 8X | 9 | 6 | 52.32 | 1.6 | 399.56
User.7: 8X | 9 | n
User.8: 0 | 3.6 | n | 6 | 6X | 3.5 | 8X | 9 | 5 | 9.5 | 2.1 | 38.52 | 33.59 | 14.39 | 4.18 | 12.31 | 77.92 | 89.32 | 99.77 | 130.53 | 137.69 | 127.98 | 176.89 | 197.5 | 298.92 | 310.32 | 320.77 | 351.53 | 358.69 | 348.98 | 376.46 | 397.89 | 418.5 | 1.6 | 428.81
User.9: 8X | 9 | n
User.10: 8X | 9 | n
User.11: 0 | 2 | 3.6 | n | 6 | 6X | 3.5 | 8X | 9 | 5 | 9.5 | 38.52 | 33.59 | 14.39 | 11.81 | 20.31 | 77.92 | 89.32 | 99.77 | 118.53 | 127.98 | 137.69 | 164.89 | 197.5 | 298.92 | 310.32 | 320.77 | 339.53 | 348.98 | 358.69 | 376.46 | 385.89 | 1.6 | 418.5 | 428.81
User.12: 0 | 2 | 3.6 | n | 6 | 6X | 3.5 | 8X | 9 | 5 | 9.5 | 38.52 | 33.59 | 14.39 | 14.31 | 21.81 | 77.92 | 89.32 | 99.77 | 118.53 | 127.98 | 137.69 | 164.89 | 197.5 | 298.92 | 310.32 | 320.77 | 339.53 | 348.98 | 358.69 | 376.46 | 385.89 | 1.6 | 418.5 | 428.81
User.13: 8X | 9 | n
User.15: 53.3 | 3.7 | n | 0 | 2 | 3.6 | 6 | 6X | 8X | 9 | 3.5 | 5 | 9.5 | 38.52 | 33.59 | 14.39 | 14.31 | 21.81 | 77.92 | 89.32 | 99.77 | 118.53 | 127.98 | 137.69 | 164.89 | 197.5 | 298.92 | 310.32 | 320.77 | 339.53 | 348.98 | 358.69 | 376.46 | 1.6 | 385.89 | 418.5 | 428.81
User.16: 8X | 9 | n
User.17: 53.3 | 3.6 | n | 0 | 2 | 6 | 6X | 8X | 9 | 3.5 | 5 | 9.5 | 38.52 | 33.59 | 14.39 | 14.31 | 21.81 | 77.92 | 89.32 | 99.77 | 118.53 | 127.98 | 137.69 | 164.89 | 197.5 | 298.92 | 310.32 | 320.77 | 339.53 | 348.98 | 358.69 | 376.46 | 385.89 | 1.6 | 418.5 | 428.81
User.18: 8X | 9 | n
User.19: TOP | 1
User.20: BOTTOM | 8
User.21: SILK-TOP
User.22: SILK-BOT
User.23: MASK-TOP
User.24: MASK-BOT
User.25: FAB
User.26: PAST-TOP
User.27: PAST-BOT
User.28: GND | 2
User.29: VCC | 4
User.30: IN1 | 3
User.31: IN2 | 6
User.32: IN3 | 5
User.33: IN4 | 7
User.34: GND1 | 7
User.35: VCC1 | 5
User.36: PANEL
User.39: DETAIL A
User.41: FIGURE | SIZE | 10.0 | 20.0 | 22.0 | 30.0 | 33.0 | 35.0 | 37.0 | 38.0 | 41.0 | 43.0 | 46.0 | 62.0 | 80.0 | 99.0 | 158.0 | 42.0 | 63.0 | 85.0 | 128.0 | 138.0 | 142.0 | 63.0x38.0 | DRILL CHART: TOP to BOTTOM | ALL UNITS ARE IN MILS | TOLERANCE | +3.0/-3.0 | +2.0/-2.0 | +4.0/-4.0 | PLATED | NON-PLATED | QTY | 268 | 176 | 216 | 297 | 16 | 48 | 4 | 32 | 36 | 12 | 40 | 18 | 8 | 2 | 6
